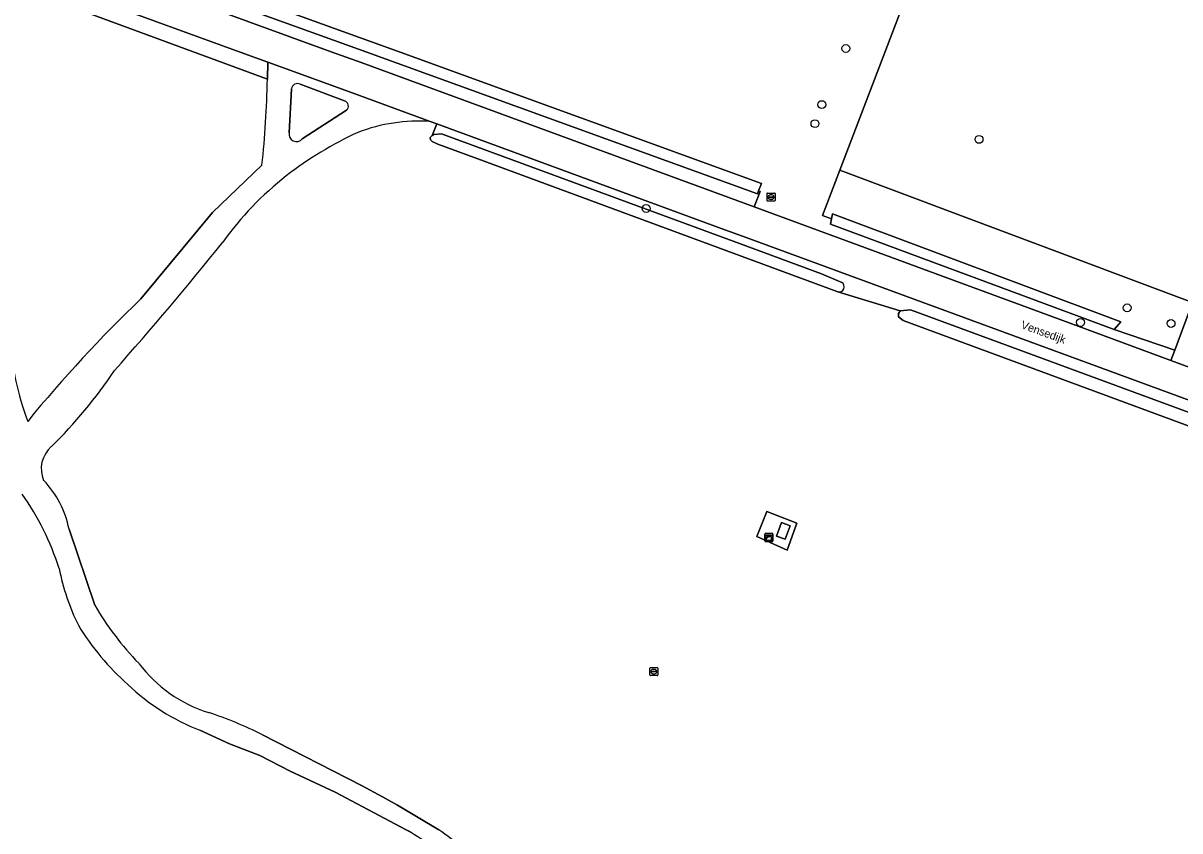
# Model space of a CAD drawing. Extents: x 156061 to 157804, y 383437 to 385640.
# Drawn here: x 156769 to 156913.5, y 384902.7 to 385003.6 of the extents above; entities that cross this region are included whole.
import ezdxf

# ---------------------------------------------------------------- set-up
doc = ezdxf.new("R2010")
doc.units = 0
for name, color, linetype in [('IMGEO_Boom', 7, 'Continuous'), ('IMGEO_Grasland_overig', 7, 'Continuous'), ('IMGEO_Groenvoorziening', 7, 'Continuous'), ('IMGEO_Kast', 7, 'Continuous'), ('IMGEO_Loofbos', 7, 'Continuous'), ('IMGEO_Openbare_ruimte_label', 7, 'Continuous'), ('IMGEO_Rijbaan_lokaal_open', 7, 'Continuous'), ('IMGEO_Rioolput', 7, 'Continuous'), ('IMGEO_Terreindeel_open', 7, 'Continuous'), ('IMGEO_Voetpad_open', 7, 'Continuous'), ('IMGEO_Waterloop', 7, 'Continuous')]:
    doc.layers.add(name, color=color, linetype=linetype)

msp = doc.modelspace()

# ---------------------------------------------------------------- linework, layer by layer
at = {"layer": 'IMGEO_Boom'}
for centre in [(156871.79, 385000.44), (156868.79, 384993.43), (156867.93, 384991.04), (156888.43, 384989.08), (156846.85, 384980.44), (156906.93, 384968.04), (156901.1, 384966.21), (156912.41, 384966.08)]:
    msp.add_circle(centre, 0.489, dxfattribs=at)
at = {"layer": 'IMGEO_Grasland_overig'}
for points in [[(156819.88, 384991.33), (156810.26, 384994.86), (156799.58, 384998.75), (156799.58, 384998.04), (156799.57, 384997.32), (156799.56, 384996.61)], [(156803.64, 384995.98), (156809.17, 384993.9)], [(156802.27, 384989.92), (156802.55, 384995.4)], [(156809.42, 384992.73), (156803.89, 384989.15)], [(156798.87, 384985.85), (156792.67, 384979.93), (156783.75, 384969.16)], [(156777.98, 384930.87), (156774.77, 384940.38)], [(156791.11, 384915.27), (156794.81, 384913.57), (156798.6, 384912.08), (156802.4, 384910.13), (156807.99, 384907.51), (156816.86, 384902.81), (156817.12, 384902.68)], [(156820.96, 384902.81), (156815.81, 384905.89), (156813.9, 384906.94), (156811.3, 384908.35), (156798.92, 384914.69)]]:
    msp.add_lwpolyline(points, dxfattribs=at)
for centre, radius, start, end in [((156672.82, 384999.27), 126.76, 353.9203, 358.7964), ((156803.3, 384995.31), 0.753, 62.5, 173.155), ((156808.98, 384993.24), 0.677, 310.0057, 73.9494), ((156818.52, 384969.92), 21.45, 86.3648, 110.9443), ((156830.33, 384947.71), 46.52, 114.7544, 127.6563), ((156803.18, 384989.74), 0.927, 168.9264, 320.2841), ((156827.33, 384952.32), 41.04, 128.2733, 144.3771), ((156485.67, 385222.85), 394.81, 318.2962, 321.3418), ((156898.42, 384849.09), 166.03, 133.6817, 140.8818), ((156806.42, 384967.34), 39.21, 184.3539, 200.1381), ((156731.56, 384992.73), 58.72, 314.2935, 326.3406), ((156775.02, 384947.92), 3.72, 131.4478, 202.9881), ((156762.54, 384937.88), 12.49, 11.577, 43.4655), ((156740.78, 384925.03), 34.37, 17.6737, 35.0214), ((156801.82, 384941.09), 28.84, 191.2458, 206.1707), ((156811.15, 384950.28), 38.43, 210.3285, 223.9421), ((156803.4, 384945.06), 32.14, 211.291, 228.5408), ((156797.39, 384934.1), 17.42, 217.0232, 252.6243), ((156800.49, 384939.98), 26.43, 225.9696, 249.2061), ((156776.9, 384870.99), 48.93, 63.2609, 71.8018), ((156800.48, 384873.95), 33.2, 46.951, 59.9263), ((156790.75, 384860.45), 52.03, 46.1397, 54.5119)]:
    msp.add_arc(centre, radius, start, end, dxfattribs=at)
at = {"layer": 'IMGEO_Groenvoorziening'}
for points in [[(156713.96, 385035.85), (156720.23, 385033.59), (156720.55, 385034.44), (156728.2, 385031.7), (156816.11, 385000), (156861.26, 384983.57), (156860.9, 384982.66), (156861.08, 384982.59), (156860.33, 384980.64), (156901.61, 384965.45), (156912.38, 384961.46), (156912.86, 384962.75), (156905.32, 384965.34), (156869.87, 384978.49), (156870, 384979.14), (156868.87, 384979.58), (156871.03, 384985.24), (156899.44, 385059.57)], [(156632.9, 385057.11), (156756.36, 385012.54), (156799.56, 384996.61), (156799.57, 384997.32), (156799.58, 384998.04), (156799.58, 384998.75), (156796.16, 385000), (156770.02, 385009.53), (156724.41, 385026.09), (156703.57, 385033.62)], [(156717.59, 385032.82), (156725.73, 385029.79), (156771.27, 385013.26), (156807.53, 385000.03), (156811.25, 384998.67), (156860.33, 384980.64), (156861.08, 384982.59), (156860.9, 384982.66), (156860.75, 384982.28), (156811.97, 385000), (156727.84, 385030.32), (156720.06, 385033.12), (156720.23, 385033.59), (156713.96, 385035.85)], [(156809.17, 384993.9), (156803.64, 384995.98)], [(156802.55, 384995.4), (156802.27, 384989.92)], [(156803.89, 384989.15), (156809.42, 384992.73)], [(157064, 384901.77), (157036.15, 384912.2), (156993.22, 384927.71), (156971.53, 384935.6), (156858.87, 384976.99), (156856.67, 384977.8), (156820.71, 384991.02), (156820.13, 384989.55), (156820.32, 384989.71), (156821.28, 384989.79), (156858.5, 384976.06), (156868.77, 384972.27), (156871.29, 384971.21)], [(156870.77, 384970.05), (156878.59, 384967.67), (156879.86, 384967.79), (156915.79, 384954.54), (156984.23, 384928.88), (156985.36, 384928.62), (156995.26, 384925.04), (157000, 384923.3), (157036.49, 384909.93), (157043.19, 384906.77), (157047.08, 384905.16), (157063.99, 384898.81)], [(157020.34, 384923.22), (157000, 384930.78), (156926.61, 384957.81), (156926.84, 384958.53), (156914.99, 384962.84), (156916.92, 384967.99), (156915.07, 384968.69), (156912.86, 384962.75), (156912.38, 384961.46), (156943.17, 384950.08), (156964.23, 384941.54), (156981.87, 384934.76), (156994.14, 384930.25), (157022.07, 384920.37), (157036.96, 384914.95), (157062, 384905.6)]]:
    msp.add_lwpolyline(points, dxfattribs=at)
for points in [[(156915.07, 384968.69), (156915.23, 384969.11), (156931.18, 385012.03), (156923.39, 385014.39), (156930.43, 385031.78), (156920.19, 385040.83), (156913.71, 385046.41), (156906.77, 385052.69), (156902.65, 385056.64), (156899.44, 385059.57), (156871.03, 384985.24)], [(156912.86, 384962.75), (156915.07, 384968.69), (156871.03, 384985.24), (156868.87, 384979.58), (156870, 384979.14), (156870.13, 384979.76), (156906.14, 384966.29), (156905.32, 384965.34)]]:
    msp.add_lwpolyline(points, close=True, dxfattribs=at)
for centre, radius, start, end in [((156803.3, 384995.31), 0.753, 62.5, 173.155), ((156808.98, 384993.24), 0.677, 310.0057, 73.9494), ((156803.18, 384989.74), 0.927, 168.9264, 320.2841), ((156870.94, 384970.67), 0.643, 254.6528, 57.2207)]:
    msp.add_arc(centre, radius, start, end, dxfattribs=at)
at = {"layer": 'IMGEO_Kast'}
for p, q in [((156861.68, 384938.92), (156861.68, 384939.76)), ((156861.68, 384939.76), (156861.68, 384938.92)), ((156861.75, 384939.84), (156862.59, 384939.84)), ((156862.59, 384939.84), (156861.75, 384939.84)), ((156862.68, 384939.77), (156862.68, 384938.93)), ((156862.68, 384938.93), (156862.68, 384939.77)), ((156862.6, 384938.84), (156861.76, 384938.84)), ((156861.76, 384938.84), (156862.6, 384938.84))]:
    msp.add_line(p, q, dxfattribs=at)
for points in [[(156861.87, 384939.63), (156862.47, 384939.63), (156862.47, 384939.55), (156861.87, 384939.55), (156861.87, 384939.63)], [(156861.87, 384939.46), (156862.47, 384939.46), (156862.47, 384938.97), (156861.87, 384938.97), (156861.87, 384939.46)]]:
    msp.add_lwpolyline(points, dxfattribs=at)
msp.add_circle((156861.96, 384939.31), 0.0377, dxfattribs=at)
for centre, start, end in [((156861.76, 384939.76), 92.4484, 184.2845), ((156861.76, 384939.76), 92.4484, 184.2845), ((156862.6, 384939.76), 2.4484, 94.2845), ((156862.6, 384939.76), 2.4484, 94.2845), ((156861.76, 384938.92), 182.4484, 274.2845), ((156861.76, 384938.92), 182.4484, 274.2845), ((156862.6, 384938.92), 272.4484, 4.2845), ((156862.6, 384938.92), 272.4484, 4.2845)]:
    msp.add_arc(centre, 0.0779, start, end, dxfattribs=at)
at = {"layer": 'IMGEO_Loofbos'}
for points in [[(156799.56, 384996.61), (156756.36, 385012.54), (156632.9, 385057.11)], [(156983.46, 384927.75), (156922.98, 384950.15), (156878.94, 384966.46), (156878.37, 384966.91), (156878.36, 384967.33), (156878.59, 384967.67), (156870.77, 384970.05), (156825.82, 384986.65), (156820.82, 384988.49), (156820.12, 384988.83), (156819.92, 384989.03), (156819.88, 384989.33), (156820.13, 384989.55), (156820.71, 384991.02), (156819.88, 384991.33)], [(156783.75, 384969.16), (156792.67, 384979.93), (156798.87, 384985.85)], [(156774.77, 384940.38), (156777.98, 384930.87)], [(156817.12, 384902.68), (156816.86, 384902.81), (156807.99, 384907.51), (156802.4, 384910.13), (156798.6, 384912.08), (156794.81, 384913.57), (156791.11, 384915.27)], [(156798.92, 384914.69), (156811.3, 384908.35), (156813.9, 384906.94), (156815.81, 384905.89), (156820.96, 384902.81)]]:
    msp.add_lwpolyline(points, dxfattribs=at)
msp.add_lwpolyline([(156864.46, 384937.75), (156860.66, 384939.46), (156861.93, 384942.59), (156865.68, 384941.12)], close=True, dxfattribs=at)
for centre, radius, start, end in [((156672.82, 384999.27), 126.76, 353.9203, 358.7964), ((156818.52, 384969.92), 21.45, 86.3648, 110.9443), ((156830.33, 384947.71), 46.52, 114.7544, 127.6563), ((156827.33, 384952.32), 41.04, 128.2733, 144.3771), ((156485.67, 385222.85), 394.81, 318.2962, 321.3418), ((156898.42, 384849.09), 166.03, 133.6817, 140.8818), ((156806.42, 384967.34), 39.21, 184.3539, 200.1381), ((156731.56, 384992.73), 58.72, 314.2935, 326.3406), ((156775.02, 384947.92), 3.72, 131.4478, 202.9881), ((156762.54, 384937.88), 12.49, 11.577, 43.4655), ((156740.78, 384925.03), 34.37, 17.6737, 35.0214), ((156801.82, 384941.09), 28.84, 191.2458, 206.1707), ((156811.15, 384950.28), 38.43, 210.3285, 223.9421), ((156803.4, 384945.06), 32.14, 211.291, 228.5408), ((156797.39, 384934.1), 17.42, 217.0232, 252.6243), ((156800.49, 384939.98), 26.43, 225.9696, 249.2061), ((156776.9, 384870.99), 48.93, 63.2609, 71.8018), ((156800.48, 384873.95), 33.2, 46.951, 59.9263), ((156790.75, 384860.45), 52.03, 46.1397, 54.5119)]:
    msp.add_arc(centre, radius, start, end, dxfattribs=at)
at = {"layer": 'IMGEO_Rijbaan_lokaal_open'}
msp.add_lwpolyline([(156724.41, 385026.09), (156770.02, 385009.53), (156796.16, 385000), (156799.58, 384998.75), (156810.26, 384994.86), (156819.88, 384991.33), (156820.71, 384991.02), (156856.67, 384977.8), (156858.87, 384976.99), (156971.53, 384935.6), (156993.22, 384927.71), (156994.14, 384930.25), (156981.87, 384934.76), (156964.23, 384941.54), (156943.17, 384950.08), (156912.38, 384961.46), (156901.61, 384965.45), (156860.33, 384980.64), (156811.25, 384998.67), (156807.53, 385000.03), (156771.27, 385013.26), (156725.73, 385029.79)], dxfattribs=at)
at = {"layer": 'IMGEO_Rioolput'}
for p, q in [((156861.95, 384981.45), (156861.95, 384982.3)), ((156862.02, 384982.38), (156862.87, 384982.38)), ((156862.2, 384981.87), (156862.2, 384981.88)), ((156862.64, 384981.83), (156862.24, 384981.83)), ((156862.25, 384981.92), (156862.65, 384981.92)), ((156862.43, 384982.15), (156862.46, 384982.15)), ((156862.46, 384981.6), (156862.43, 384981.6)), ((156862.69, 384981.88), (156862.69, 384981.87)), ((156862.95, 384982.3), (156862.95, 384981.45)), ((156862.87, 384981.37), (156862.02, 384981.37)), ((156847.31, 384922.16), (156847.31, 384923.01)), ((156847.39, 384923.08), (156848.24, 384923.08)), ((156847.57, 384922.58), (156847.57, 384922.59)), ((156848.01, 384922.54), (156847.61, 384922.54)), ((156847.62, 384922.63), (156848.01, 384922.63)), ((156847.8, 384922.86), (156847.83, 384922.86)), ((156847.82, 384922.3), (156847.8, 384922.3)), ((156848.06, 384922.59), (156848.06, 384922.58)), ((156848.31, 384923.01), (156848.31, 384922.16)), ((156848.24, 384922.08), (156847.39, 384922.08))]:
    msp.add_line(p, q, dxfattribs=at)
for points in [[(156861.95, 384981.45), (156861.95, 384982.3)], [(156862.02, 384982.38), (156862.87, 384982.38)], [(156862.95, 384982.3), (156862.95, 384981.45)], [(156862.87, 384981.37), (156862.02, 384981.37)], [(156847.31, 384922.16), (156847.31, 384923.01)], [(156847.39, 384923.08), (156848.24, 384923.08)], [(156848.31, 384923.01), (156848.31, 384922.16)], [(156848.24, 384922.08), (156847.39, 384922.08)]]:
    msp.add_lwpolyline(points, dxfattribs=at)
for centre, radius, start, end in [((156862.02, 384982.3), 0.0765, 91.552, 178.448), ((156862.02, 384982.3), 0.0765, 91.552, 178.448), ((156862.02, 384981.45), 0.0765, 181.552, 268.448), ((156862.02, 384981.45), 0.0765, 181.552, 268.448), ((156862.25, 384981.88), 0.0403, 85.8775, 175.7526), ((156862.24, 384981.87), 0.0366, 178.938, 274.7102), ((156862.65, 384981.87), 0.043, 264.8664, 352.4533), ((156862.65, 384981.88), 0.0386, 1.7309, 96.639), ((156862.87, 384982.3), 0.0765, 1.552, 88.448), ((156862.87, 384982.3), 0.0765, 1.552, 88.448), ((156862.87, 384981.45), 0.0765, 271.552, 358.448), ((156862.87, 384981.45), 0.0765, 271.552, 358.448), ((156847.39, 384923.01), 0.0765, 91.552, 178.448), ((156847.39, 384923.01), 0.0765, 91.552, 178.448), ((156847.61, 384922.59), 0.0403, 85.8775, 175.7526), ((156847.61, 384922.58), 0.0366, 178.938, 274.7102), ((156848.02, 384922.59), 0.0386, 1.7309, 96.639), ((156848.01, 384922.58), 0.043, 264.8664, 352.4533), ((156848.24, 384923.01), 0.0765, 1.552, 88.448), ((156848.24, 384923.01), 0.0765, 1.552, 88.448), ((156847.39, 384922.16), 0.0765, 181.552, 268.448), ((156847.39, 384922.16), 0.0765, 181.552, 268.448), ((156848.24, 384922.16), 0.0765, 271.552, 358.448), ((156848.24, 384922.16), 0.0765, 271.552, 358.448)]:
    msp.add_arc(centre, radius, start, end, dxfattribs=at)
for centre, major_axis, ratio, start_param, end_param in [((156862.43, 384981.87), (-0.387, 0.002), 0.722429, 4.712389, 7.853982), ((156862.46, 384981.87), (-0.39, 0.002), 0.717154, 1.570796, 4.712389), ((156847.8, 384922.58), (-0.387, 0.002), 0.722429, 4.712389, 7.853982), ((156847.82, 384922.58), (-0.39, 0.002), 0.717154, 1.570796, 4.712389)]:
    msp.add_ellipse(centre, major_axis=major_axis, ratio=ratio, start_param=start_param, end_param=end_param, dxfattribs=at)
at = {"layer": 'IMGEO_Terreindeel_open'}
msp.add_lwpolyline([(156864.83, 384940.8), (156863.75, 384941.2), (156863.15, 384939.5), (156864.21, 384939.11)], close=True, dxfattribs=at)
at = {"layer": 'IMGEO_Voetpad_open'}
for points in [[(156865.68, 384941.12), (156861.93, 384942.59), (156860.66, 384939.46), (156864.46, 384937.75)], [(156864.21, 384939.11), (156863.15, 384939.5), (156863.75, 384941.2), (156864.83, 384940.8)]]:
    msp.add_lwpolyline(points, close=True, dxfattribs=at)
at = {"layer": 'IMGEO_Waterloop'}
for points in [[(156728.2, 385031.7), (156720.55, 385034.44), (156720.23, 385033.59), (156720.06, 385033.12), (156727.84, 385030.32), (156811.97, 385000), (156860.75, 384982.28), (156860.9, 384982.66), (156861.26, 384983.57), (156816.11, 385000)], [(156906.14, 384966.29), (156870.13, 384979.76), (156870, 384979.14), (156869.87, 384978.49), (156905.32, 384965.34)]]:
    msp.add_lwpolyline(points, close=True, dxfattribs=at)
for points in [[(156871.29, 384971.21), (156868.77, 384972.27), (156858.5, 384976.06), (156821.28, 384989.79), (156820.32, 384989.71), (156820.13, 384989.55), (156819.88, 384989.33), (156819.92, 384989.03), (156820.12, 384988.83), (156820.82, 384988.49), (156825.82, 384986.65), (156870.77, 384970.05)], [(156915.79, 384954.54), (156879.86, 384967.79), (156878.59, 384967.67), (156878.36, 384967.33), (156878.37, 384966.91), (156878.94, 384966.46), (156922.98, 384950.15), (156983.46, 384927.75)]]:
    msp.add_lwpolyline(points, dxfattribs=at)
msp.add_arc((156870.94, 384970.67), 0.643, 254.6528, 57.2207, dxfattribs=at)

# ---------------------------------------------------------------- texts
at = {"layer": 'IMGEO_Openbare_ruimte_label'}
msp.add_text('Vensedijk', height=1, rotation=340.1882, dxfattribs=at).set_placement((156893.59, 384965.51))

doc.saveas('drawing.dxf')
